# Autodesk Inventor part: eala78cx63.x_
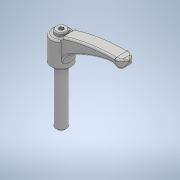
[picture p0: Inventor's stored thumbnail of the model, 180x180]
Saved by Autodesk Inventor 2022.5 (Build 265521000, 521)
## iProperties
Created: 2018-05
Part Number: eala78cx63.x_
Material: 一般
Document SubType Name: Modeling
Designer: imaocorp
Density: 1 g/cm^3
Appearance: 既定
Sending System: SOLIDWORKS 2016-2016286
MC: AMD64
MC_MODEL: AMD64 Family 21 Model 2 Stepping 0, AuthenticAMD
OS: Windows_NT
FRU: Parasolid Version 28.0, build 224,  7-29-2016
FORMAT: text
GUISE: transmit
KEY: eala78cx63
FILE: eala78cx63.x_t
DATE: Fri May 18 11:32:39 2018
Author: imaocorp
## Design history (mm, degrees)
feature "Base1"
node "ソリッド1"
